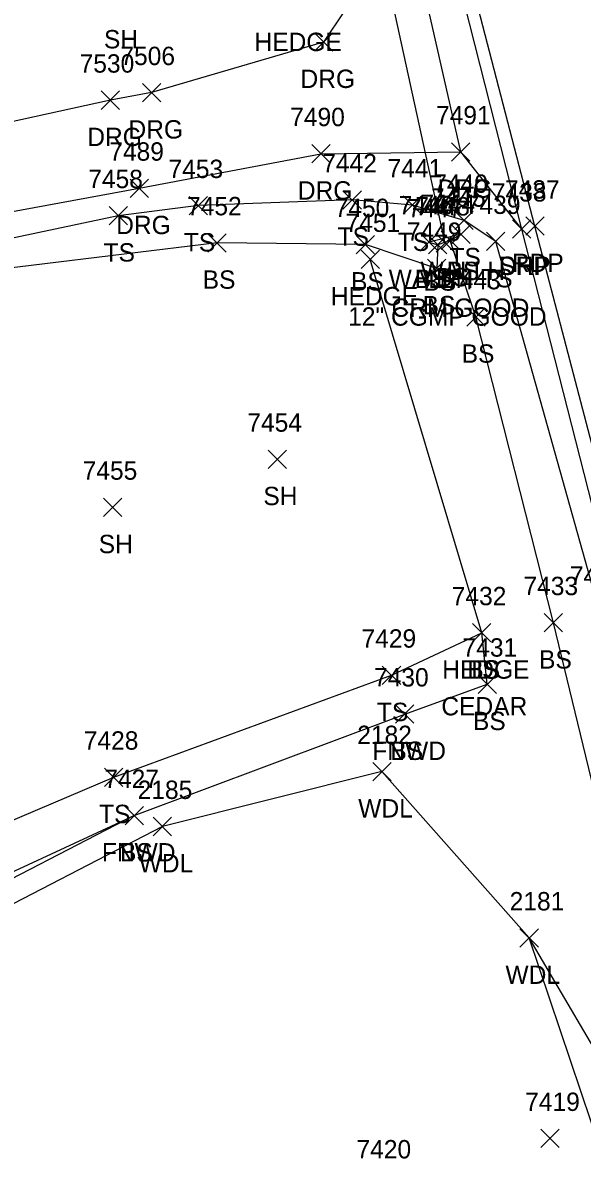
# Model space of a CAD drawing. Extents: x 1439173 to 1457902, y 641926 to 659889.
# Drawn here: x 1448564.6 to 1448625.5, y 644187.7 to 644311.8 of the extents above; entities that cross this region are included whole.
import ezdxf

# ---------------------------------------------------------------- set-up
doc = ezdxf.new("R2010")
doc.units = 0
for name, color, linetype in [('D_A', 7, 'Continuous'), ('D_C', 7, 'Continuous'), ('D_I', 7, 'Continuous'), ('D_TIC', 7, 'Continuous'), ('DCP', 7, 'Continuous'), ('DHW', 7, 'Continuous'), ('L_A', 7, 'Continuous'), ('L_C', 7, 'Continuous'), ('L_I', 7, 'Continuous'), ('L_TIC', 7, 'Continuous'), ('LAHR', 7, 'Continuous'), ('LAWA', 7, 'Continuous'), ('LELB', 7, 'Continuous'), ('LFNC', 7, 'Continuous'), ('P_A', 7, 'Continuous'), ('P_I', 7, 'Continuous'), ('P_TIC', 7, 'Continuous'), ('PET', 7, 'Continuous'), ('PSP', 7, 'Continuous'), ('R_A', 7, 'Continuous'), ('R_I', 7, 'Continuous'), ('R_TIC', 7, 'Continuous'), ('RDG', 7, 'Continuous'), ('RDP', 7, 'Continuous')]:
    doc.layers.add(name, color=color, linetype=linetype)

msp = doc.modelspace()

# ---------------------------------------------------------------- linework, layer by layer
at = {"layer": 'D_TIC'}
for points in [[(1448607.83, 644286.92), (1448609.83, 644288.92)], [(1448609.83, 644286.92), (1448607.83, 644288.92)], [(1448609.58, 644286.81), (1448611.58, 644288.81)], [(1448611.58, 644286.81), (1448609.58, 644288.81)], [(1448611.29, 644287.77), (1448613.29, 644289.77)], [(1448613.29, 644287.77), (1448611.29, 644289.77)]]:
    msp.add_lwpolyline(points, dxfattribs=at)
at = {"layer": 'DCP'}
msp.add_lwpolyline([(1448610.58, 644287.81), (1448601.84, 644327.87)], dxfattribs=at)
at = {"layer": 'DHW'}
msp.add_lwpolyline([(1448612.29, 644288.77), (1448608.83, 644287.92)], dxfattribs=at)
at = {"layer": 'L_TIC'}
for points in [[(1448582.71, 644290.89), (1448584.71, 644292.89)], [(1448584.71, 644290.89), (1448582.71, 644292.89)], [(1448599.45, 644291.51), (1448601.45, 644293.51)], [(1448601.45, 644291.51), (1448599.45, 644293.51)], [(1448606, 644290.95), (1448608, 644292.95)], [(1448608, 644290.95), (1448606, 644292.95)], [(1448573.97, 644289.79), (1448575.97, 644291.79)], [(1448575.97, 644289.79), (1448573.97, 644291.79)], [(1448611.63, 644289.28), (1448613.63, 644291.28)], [(1448613.63, 644289.28), (1448611.63, 644291.28)], [(1448584.73, 644286.83), (1448586.73, 644288.83)], [(1448586.73, 644286.83), (1448584.73, 644288.83)], [(1448607.83, 644286.92), (1448609.83, 644288.92)], [(1448609.83, 644286.92), (1448607.83, 644288.92)], [(1448610.13, 644287.09), (1448612.13, 644289.09)], [(1448612.13, 644287.09), (1448610.13, 644289.09)], [(1448610.13, 644287.09), (1448612.13, 644289.09)], [(1448612.13, 644287.09), (1448610.13, 644289.09)], [(1448611.29, 644287.77), (1448613.29, 644289.77)], [(1448613.29, 644287.77), (1448611.29, 644289.77)], [(1448615.09, 644286.98), (1448617.09, 644288.98)], [(1448617.09, 644286.98), (1448615.09, 644288.98)], [(1448600.89, 644286.64), (1448602.89, 644288.64)], [(1448602.89, 644286.64), (1448600.89, 644288.64)], [(1448608.77, 644286.62), (1448610.77, 644288.62)], [(1448610.77, 644286.62), (1448608.77, 644288.62)], [(1448608.77, 644286.62), (1448610.77, 644288.62)], [(1448610.77, 644286.62), (1448608.77, 644288.62)], [(1448601.42, 644285.02), (1448603.42, 644287.02)], [(1448603.42, 644285.02), (1448601.42, 644287.02)], [(1448608.66, 644284.05), (1448610.66, 644286.05)], [(1448610.66, 644284.05), (1448608.66, 644286.05)], [(1448612.93, 644278.77), (1448614.93, 644280.77)], [(1448614.93, 644278.77), (1448612.93, 644280.77)], [(1448591.29, 644263.26), (1448593.29, 644265.26)], [(1448593.29, 644263.26), (1448591.29, 644265.26)], [(1448573.36, 644258.03), (1448575.36, 644260.03)], [(1448575.36, 644258.03), (1448573.36, 644260.03)], [(1448621.36, 644245.46), (1448623.36, 644247.46)], [(1448623.36, 644245.46), (1448621.36, 644247.46)], [(1448613.55, 644244.36), (1448615.55, 644246.36)], [(1448615.55, 644244.36), (1448613.55, 644246.36)], [(1448613.55, 644244.36), (1448615.55, 644246.36)], [(1448615.55, 644244.36), (1448613.55, 644246.36)], [(1448613.55, 644244.36), (1448615.55, 644246.36)], [(1448615.55, 644244.36), (1448613.55, 644246.36)], [(1448603.73, 644239.74), (1448605.73, 644241.74)], [(1448605.73, 644239.74), (1448603.73, 644241.74)], [(1448614.16, 644238.76), (1448616.16, 644240.76)], [(1448616.16, 644238.76), (1448614.16, 644240.76)], [(1448605.17, 644235.51), (1448607.17, 644237.51)], [(1448607.17, 644235.51), (1448605.17, 644237.51)], [(1448605.17, 644235.51), (1448607.17, 644237.51)], [(1448607.17, 644235.51), (1448605.17, 644237.51)], [(1448573.48, 644228.63), (1448575.48, 644230.63)], [(1448575.48, 644228.63), (1448573.48, 644230.63)], [(1448602.69, 644229.24), (1448604.69, 644231.24)], [(1448604.69, 644229.24), (1448602.69, 644231.24)], [(1448575.72, 644224.45), (1448577.72, 644226.45)], [(1448577.72, 644224.45), (1448575.72, 644226.45)], [(1448575.72, 644224.45), (1448577.72, 644226.45)], [(1448577.72, 644224.45), (1448575.72, 644226.45)], [(1448578.78, 644223.26), (1448580.78, 644225.26)], [(1448580.78, 644223.26), (1448578.78, 644225.26)], [(1448618.72, 644211.12), (1448620.72, 644213.12)], [(1448620.72, 644211.12), (1448618.72, 644213.12)], [(1448620.99, 644189.28), (1448622.99, 644191.28)], [(1448622.99, 644189.28), (1448620.99, 644191.28)]]:
    msp.add_lwpolyline(points, dxfattribs=at)
at = {"layer": 'LAHR'}
msp.add_lwpolyline([(1448614.55, 644245.36), (1448602.42, 644286.02)], dxfattribs=at)
at = {"layer": 'LAWA'}
msp.add_lwpolyline([(1448548.25, 644134.82), (1448578.96, 644146.48), (1448568.63, 644182.21), (1448589.69, 644175.66), (1448602.22, 644178.06), (1448630.41, 644168.54), (1448628.73, 644185.43), (1448619.72, 644212.12), (1448603.69, 644230.24), (1448579.78, 644224.26), (1448558.44, 644213.23), (1448548.55, 644204.94)], dxfattribs=at)
at = {"layer": 'LELB'}
for points in [[(1448714.17, 644015.51), (1448690.32, 644058.37), (1448680.4, 644064.04), (1448674.64, 644080.95), (1448666.72, 644090.45), (1448667.24, 644111.7), (1448656.59, 644145.17), (1448648.16, 644169.82), (1448640.45, 644195.85), (1448627.41, 644247.58), (1448616.09, 644287.98), (1448612.63, 644290.28), (1448607, 644291.95), (1448600.45, 644292.51), (1448583.71, 644291.89), (1448574.97, 644290.79), (1448548.7, 644285.2), (1448529.49, 644265.1), (1448525.79, 644264.84)], [(1448611.13, 644288.09), (1448612.29, 644288.77)], [(1448649.96, 644144.44), (1448641.08, 644165.22), (1448634.47, 644196.59), (1448622.36, 644246.46), (1448613.93, 644279.77), (1448611.13, 644288.09), (1448609.77, 644287.62), (1448609.66, 644285.05), (1448601.89, 644287.64), (1448585.73, 644287.83), (1448555.33, 644284.13), (1448549.99, 644262.79), (1448539.56, 644266.19), (1448544.28, 644240.56), (1448539.5, 644223.13), (1448529.99, 644215.09)], [(1448608.83, 644287.92), (1448609.77, 644287.62)], [(1448532.06, 644208.13), (1448552.52, 644220.29), (1448574.48, 644229.63), (1448604.73, 644240.74), (1448614.55, 644245.36)], [(1448606.17, 644236.51), (1448615.16, 644239.76), (1448614.55, 644245.36)], [(1448534.89, 644193.73), (1448556.15, 644215.95), (1448576.72, 644225.45)], [(1448629.92, 644194.78), (1448619.72, 644212.12)]]:
    msp.add_lwpolyline(points, dxfattribs=at)
at = {"layer": 'LFNC'}
for points in [[(1448576.72, 644225.45), (1448606.17, 644236.51)], [(1448576.72, 644225.45), (1448557.02, 644215.3)]]:
    msp.add_lwpolyline(points, dxfattribs=at)
at = {"layer": 'P_TIC'}
for points in [[(1448617.92, 644288.33), (1448619.92, 644290.33)], [(1448619.92, 644288.33), (1448617.92, 644290.33)], [(1448619.35, 644288.65), (1448621.35, 644290.65)], [(1448621.35, 644288.65), (1448619.35, 644290.65)]]:
    msp.add_lwpolyline(points, dxfattribs=at)
at = {"layer": 'PET'}
msp.add_lwpolyline([(1448719.14, 644017.8), (1448697.57, 644061.64), (1448675.31, 644114.87), (1448662.79, 644147.1), (1448645.62, 644197.83), (1448630.96, 644249.03), (1448620.35, 644289.65), (1448608.04, 644337.09), (1448599.93, 644371.01), (1448591.93, 644405.93), (1448587.28, 644423.3), (1448576.41, 644471.58), (1448564.34, 644525.55), (1448554.28, 644567.62), (1448542.43, 644618.88), (1448530.58, 644668.68), (1448520.66, 644712.53), (1448508.59, 644763.84)], dxfattribs=at)
at = {"layer": 'PSP'}
msp.add_lwpolyline([(1448718.77, 644017.47), (1448697.57, 644061.64), (1448674.36, 644114.53), (1448661.94, 644146.48), (1448644.48, 644197.51), (1448629.33, 644248.49), (1448618.92, 644289.33), (1448599.59, 644365.52), (1448590.65, 644405.32), (1448585.9, 644422.84), (1448574.75, 644471.24), (1448562.25, 644524.96), (1448552.68, 644566.87), (1448540.59, 644618.38), (1448529.07, 644667.76), (1448518.88, 644712.4), (1448506.69, 644763.58)], dxfattribs=at)
at = {"layer": 'R_TIC'}
for points in [[(1448596.33, 644308.7), (1448598.33, 644310.7)], [(1448598.33, 644308.7), (1448596.33, 644310.7)], [(1448577.6, 644303.19), (1448579.6, 644305.19)], [(1448579.6, 644303.19), (1448577.6, 644305.19)], [(1448573.12, 644302.37), (1448575.12, 644304.37)], [(1448575.12, 644302.37), (1448573.12, 644304.37)], [(1448611.27, 644296.74), (1448613.27, 644298.74)], [(1448613.27, 644296.74), (1448611.27, 644298.74)], [(1448611.27, 644296.74), (1448613.27, 644298.74)], [(1448613.27, 644296.74), (1448611.27, 644298.74)], [(1448596.05, 644296.54), (1448598.05, 644298.54)], [(1448598.05, 644296.54), (1448596.05, 644298.54)], [(1448576.27, 644292.78), (1448578.27, 644294.78)], [(1448578.27, 644292.78), (1448576.27, 644294.78)], [(1448617.92, 644288.33), (1448619.92, 644290.33)], [(1448619.92, 644288.33), (1448617.92, 644290.33)]]:
    msp.add_lwpolyline(points, dxfattribs=at)
at = {"layer": 'RDG'}
for points in [[(1448606.48, 644323.37), (1448597.33, 644309.7), (1448578.6, 644304.19), (1448574.12, 644303.37), (1448553.39, 644298.84), (1448535.28, 644298), (1448519.18, 644302.56), (1448504.89, 644310.79), (1448491.04, 644331.59), (1448480.63, 644355.14), (1448479.22, 644369.86), (1448486.52, 644382.93), (1448496.26, 644389.27), (1448504.76, 644392.58), (1448519.36, 644390.03), (1448540.82, 644382.24), (1448557.71, 644376.41), (1448570.67, 644374.36), (1448583.95, 644372.45), (1448591.2, 644370.91), (1448599.59, 644365.52)], [(1448515.15, 644281.74), (1448531.84, 644285.52), (1448552.99, 644289.31), (1448577.27, 644293.78), (1448597.05, 644297.54), (1448612.27, 644297.74)]]:
    msp.add_lwpolyline(points, dxfattribs=at)
at = {"layer": 'RDP'}
msp.add_lwpolyline([(1448618.92, 644289.33), (1448612.27, 644297.74), (1448606.48, 644323.37)], dxfattribs=at)

# ---------------------------------------------------------------- texts
at = {"layer": 'D_A'}
for s, p in [('WALLH', (1448607.88, 644283.77)), ('WALLH', (1448604.42, 644282.92)), ('P', (1448609.96, 644282.81))]:
    msp.add_text(s, height=2, dxfattribs=at).set_placement(p)
at = {"layer": 'D_C'}
for s, p in [('CRM GOOD', (1448604.74, 644279.77)), ('12" CGMP GOOD', (1448600.01, 644278.81))]:
    msp.add_text(s, height=2, dxfattribs=at).set_placement(p)
at = {"layer": 'D_I'}
for s, p in [('7445', (1448609.03, 644291.77)), ('7446', (1448605.51, 644290.92)), ('7448', (1448607.32, 644290.81))]:
    msp.add_text(s, height=2, dxfattribs=at).set_placement(p)
at = {"layer": 'L_A'}
for s, p in [('SH', (1448573.42, 644309.01)), ('HEDGE', (1448589.81, 644308.72)), ('TS', (1448582.12, 644286.89)), ('TS', (1448598.86, 644287.51)), ('TS', (1448605.41, 644286.95)), ('TS', (1448573.38, 644285.79)), ('TS', (1448611.04, 644285.28)), ('BS', (1448607.27, 644282.92)), ('BS', (1448609.58, 644283.09)), ('BS', (1448609.58, 644283.09)), ('BS', (1448610.73, 644283.77)), ('TS', (1448614.5, 644282.98)), ('BS', (1448584.17, 644282.83)), ('BS', (1448600.33, 644282.64)), ('BS', (1448608.21, 644282.62)), ('BS', (1448608.21, 644282.62)), ('HEDGE', (1448598.12, 644281.02)), ('BS', (1448608.11, 644280.05)), ('BS', (1448612.37, 644274.77)), ('SH', (1448590.78, 644259.26)), ('SH', (1448572.85, 644254.03)), ('BS', (1448620.8, 644241.46)), ('HEDGE', (1448610.25, 644240.36)), ('TS', (1448612.96, 644240.36)), ('BS', (1448612.99, 644240.36)), ('TS', (1448603.14, 644235.74)), ('BS', (1448613.6, 644234.76)), ('FNWD', (1448602.64, 644231.51)), ('BS', (1448604.61, 644231.51)), ('TS', (1448572.89, 644224.63)), ('WDL', (1448601.11, 644225.24)), ('FNWD', (1448573.19, 644220.45)), ('BS', (1448575.17, 644220.45)), ('WDL', (1448577.2, 644219.26)), ('WDL', (1448617.14, 644207.12))]:
    msp.add_text(s, height=2, dxfattribs=at).set_placement(p)
at = {"layer": 'L_C'}
msp.add_text('CEDAR', height=2, dxfattribs=at).set_placement((1448610.16, 644236.36))
at = {"layer": 'L_I'}
for s, p in [('7442', (1448597.19, 644295.51)), ('7453', (1448580.45, 644294.89)), ('7441', (1448604.3, 644294.95)), ('7458', (1448571.71, 644293.79)), ('7440', (1448609.28, 644293.28)), ('7445', (1448609.03, 644291.77)), ('7452', (1448582.47, 644290.83)), ('7450', (1448598.54, 644290.64)), ('7446', (1448605.51, 644290.92)), ('7447', (1448606.51, 644290.62)), ('7447', (1448606.51, 644290.62)), ('7444', (1448607.88, 644291.09)), ('7444', (1448607.88, 644291.09)), ('7439', (1448612.83, 644290.98)), ('7451', (1448599.73, 644289.02)), ('7449', (1448606.4, 644288.05)), ('7443', (1448610.67, 644282.77)), ('7454', (1448589.03, 644267.26)), ('7455', (1448571.1, 644262.03)), ('7433', (1448619.1, 644249.46)), ('7434', (1448624.15, 644250.58)), ('7432', (1448611.29, 644248.36)), ('7432', (1448611.29, 644248.36)), ('7432', (1448611.29, 644248.36)), ('7429', (1448601.47, 644243.74)), ('7431', (1448612.47, 644242.76)), ('7430', (1448602.83, 644239.51)), ('7430', (1448602.83, 644239.51)), ('7428', (1448571.22, 644232.63)), ('2182', (1448601, 644233.24)), ('7427', (1448573.46, 644228.45)), ('7427', (1448573.46, 644228.45)), ('2185', (1448577.09, 644227.26)), ('2181', (1448617.6, 644215.12)), ('7419', (1448619.29, 644193.28)), ('7420', (1448600.92, 644188.11))]:
    msp.add_text(s, height=2, dxfattribs=at).set_placement(p)
at = {"layer": 'P_A'}
for s, p in [('SHP', (1448616.45, 644284.33)), ('RDP', (1448617.84, 644284.65))]:
    msp.add_text(s, height=2, dxfattribs=at).set_placement(p)
at = {"layer": 'P_I'}
for s, p in [('7438', (1448615.66, 644292.33)), ('7437', (1448617.09, 644292.65))]:
    msp.add_text(s, height=2, dxfattribs=at).set_placement(p)
at = {"layer": 'R_A'}
for s, p in [('DRG', (1448594.82, 644304.7)), ('DRG', (1448576.09, 644299.19)), ('DRG', (1448571.6, 644298.37)), ('DRG', (1448594.53, 644292.54)), ('DRG', (1448609.76, 644292.74)), ('DRP', (1448609.76, 644292.74)), ('DRG', (1448574.75, 644288.78)), ('DRP', (1448616.41, 644284.33))]:
    msp.add_text(s, height=2, dxfattribs=at).set_placement(p)
at = {"layer": 'R_I'}
for s, p in [('7506', (1448575.21, 644307.19)), ('7530', (1448570.77, 644306.37)), ('7490', (1448593.7, 644300.54)), ('7491', (1448609.58, 644300.74)), ('7491', (1448609.58, 644300.74)), ('7489', (1448574, 644296.78)), ('7438', (1448615.66, 644292.33))]:
    msp.add_text(s, height=2, dxfattribs=at).set_placement(p)

doc.saveas('drawing.dxf')
